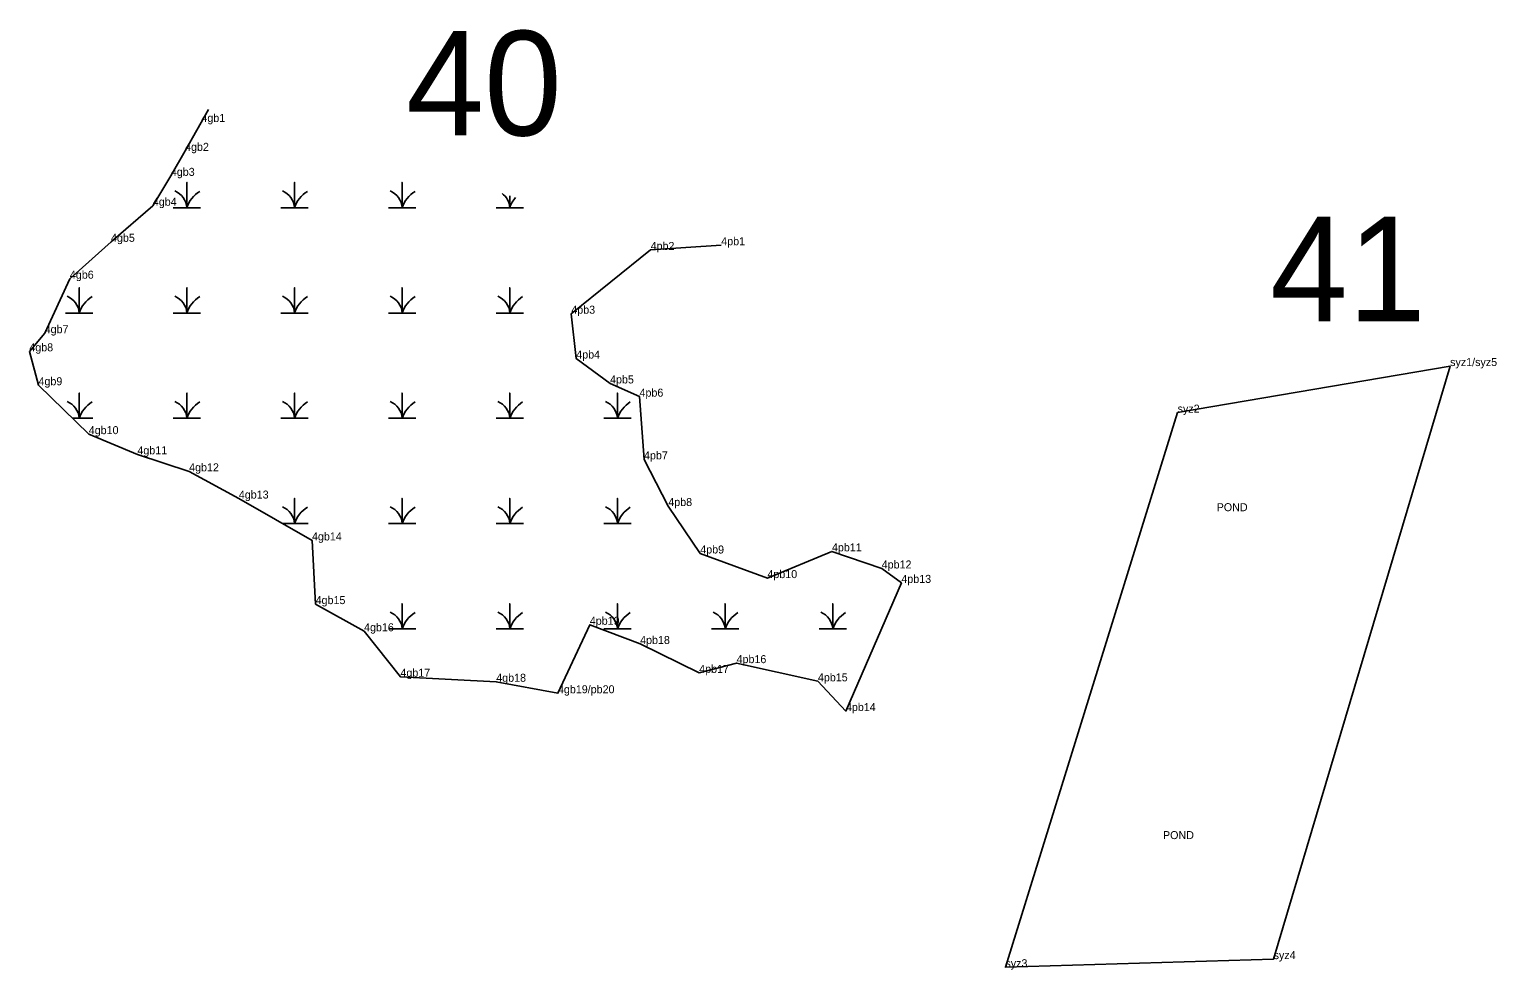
# Model space of a CAD drawing. Extents: x 2072529 to 2268796, y 436423 to 470397.
# Drawn here: x 2107562 to 2108478, y 456169 to 456756 of the extents above; entities that cross this region are included whole.
import ezdxf

# ---------------------------------------------------------------- set-up
doc = ezdxf.new("R2010")
doc.units = 0
for name, color, linetype in [('Default', 7, 'Continuous'), ('Exist Environmental Wetland Boundary', 7, 'Continuous'), ('Exist Environmental Wetland Boundary Cogo Comment', 7, 'Continuous'), ('Exist Environmental Wetland Boundary Cogo Point CELL', 7, 'Continuous'), ('Exist Hydro Jurisdictional Stream or Body of Water NEU Mitigable', 7, 'Continuous'), ('Exist Hydro Jurisdictional Stream or Body of Water NEU Mitigable Cogo Comment', 7, 'Continuous'), ('Exist Hydro Swamp or Marsh', 7, 'Continuous')]:
    doc.layers.add(name, color=color, linetype=linetype)

msp = doc.modelspace()

# ---------------------------------------------------------------- linework, layer by layer
at = {"layer": 'Exist Environmental Wetland Boundary'}
msp.add_lwpolyline([(2107673.67, 456706.2), (2107659.06, 456680.3), (2107650.18, 456664.67), (2107638.9, 456646.02), (2107612.8, 456623.48), (2107587.1, 456600.42), (2107571.35, 456566.38), (2107561.78, 456555.03), (2107567.49, 456533.84), (2107598.9, 456503.29), (2107629.27, 456490.66), (2107661.59, 456480.04), (2107692.65, 456463.02), (2107738.34, 456436.87), (2107740.6, 456397.08), (2107770.87, 456380.11), (2107793.58, 456351.7), (2107853.42, 456348.56), (2107891.98, 456341.37), (2107911.87, 456384.17), (2107943.3, 456372.16), (2107980.19, 456354.11), (2108003.54, 456360.19), (2108054.36, 456348.84), (2108071.85, 456330.26), (2108106.48, 456410.34), (2108094.21, 456419.35), (2108063.12, 456430.04), (2108022.81, 456413.35), (2107980.85, 456428.71), (2107960.9, 456458.37), (2107945.74, 456487.53), (2107942.92, 456526.73), (2107924.53, 456534.97), (2107903.4, 456550.54), (2107900.32, 456578.54), (2107949.86, 456618.38), (2107993.96, 456621.34)], dxfattribs=at)
at = {"layer": 'Exist Environmental Wetland Boundary Cogo Point CELL'}
for p, q in [((2107669.26, 456698.37), (2107669.26, 456698.37)), ((2107659.06, 456680.3), (2107659.06, 456680.3)), ((2107650.18, 456664.67), (2107650.18, 456664.67)), ((2107638.9, 456646.02), (2107638.9, 456646.02)), ((2107612.8, 456623.48), (2107612.8, 456623.48)), ((2107949.86, 456618.38), (2107949.86, 456618.38)), ((2107993.96, 456621.34), (2107993.96, 456621.34)), ((2107587.1, 456600.42), (2107587.1, 456600.42)), ((2107900.32, 456578.54), (2107900.32, 456578.54)), ((2107571.35, 456566.38), (2107571.35, 456566.38)), ((2107561.78, 456555.03), (2107561.78, 456555.03)), ((2107903.4, 456550.54), (2107903.4, 456550.54)), ((2108449.26, 456545.83), (2108449.26, 456545.83)), ((2108449.26, 456545.83), (2108449.26, 456545.83)), ((2107567.49, 456533.84), (2107567.49, 456533.84)), ((2107924.53, 456534.97), (2107924.53, 456534.97)), ((2107942.92, 456526.73), (2107942.92, 456526.73)), ((2108279.04, 456516.71), (2108279.04, 456516.71)), ((2108279.04, 456516.71), (2108279.04, 456516.71)), ((2107598.9, 456503.29), (2107598.9, 456503.29)), ((2107629.27, 456490.66), (2107629.27, 456490.66)), ((2107661.59, 456480.04), (2107661.59, 456480.04)), ((2107945.74, 456487.53), (2107945.74, 456487.53)), ((2107692.65, 456463.02), (2107692.65, 456463.02)), ((2107960.9, 456458.37), (2107960.9, 456458.37)), ((2107738.34, 456436.87), (2107738.34, 456436.87)), ((2107980.85, 456428.71), (2107980.85, 456428.71)), ((2108063.12, 456430.04), (2108063.12, 456430.04)), ((2108094.21, 456419.35), (2108094.21, 456419.35)), ((2108022.81, 456413.35), (2108022.81, 456413.35)), ((2108106.48, 456410.34), (2108106.48, 456410.34)), ((2107740.6, 456397.08), (2107740.6, 456397.08)), ((2107770.87, 456380.11), (2107770.87, 456380.11)), ((2107911.87, 456384.17), (2107911.87, 456384.17)), ((2107943.3, 456372.16), (2107943.3, 456372.16)), ((2108003.54, 456360.19), (2108003.54, 456360.19)), ((2107793.58, 456351.7), (2107793.58, 456351.7)), ((2107980.19, 456354.11), (2107980.19, 456354.11)), ((2107853.42, 456348.56), (2107853.42, 456348.56)), ((2107891.98, 456341.37), (2107891.98, 456341.37)), ((2108054.36, 456348.84), (2108054.36, 456348.84)), ((2108071.85, 456330.26), (2108071.85, 456330.26)), ((2108171.47, 456170.18), (2108171.47, 456170.18)), ((2108171.47, 456170.18), (2108171.47, 456170.18)), ((2108339.01, 456175.25), (2108339.01, 456175.25)), ((2108339.01, 456175.25), (2108339.01, 456175.25))]:
    msp.add_line(p, q, dxfattribs=at)
at = {"layer": 'Exist Hydro Jurisdictional Stream or Body of Water NEU Mitigable'}
msp.add_lwpolyline([(2108279.04, 456516.71), (2108449.26, 456545.83), (2108339.01, 456175.25), (2108171.47, 456170.18)], close=True, dxfattribs=at)
at = {"layer": 'Exist Hydro Swamp or Marsh'}
for points in [[(2107651.55, 456644.78), (2107660.16, 456644.78), (2107660.16, 456660.56), (2107660.16, 456644.78), (2107668.76, 456644.78)], [(2107718.8, 456644.78), (2107727.41, 456644.78), (2107727.41, 456660.56), (2107727.41, 456644.78), (2107736.01, 456644.78)], [(2107786.05, 456644.78), (2107794.66, 456644.78), (2107794.66, 456660.56), (2107794.66, 456644.78), (2107803.26, 456644.78)], [(2107853.3, 456644.78), (2107861.91, 456644.78), (2107861.91, 456652.27)], [(2107861.91, 456652.27), (2107861.91, 456644.78), (2107870.51, 456644.78)], [(2107584.3, 456578.98), (2107592.91, 456578.98), (2107592.91, 456594.76), (2107592.91, 456578.98), (2107601.51, 456578.98)], [(2107651.55, 456578.98), (2107660.16, 456578.98), (2107660.16, 456594.76), (2107660.16, 456578.98), (2107668.76, 456578.98)], [(2107718.8, 456578.98), (2107727.41, 456578.98), (2107727.41, 456594.76), (2107727.41, 456578.98), (2107736.01, 456578.98)], [(2107786.05, 456578.98), (2107794.66, 456578.98), (2107794.66, 456594.76), (2107794.66, 456578.98), (2107803.26, 456578.98)], [(2107853.3, 456578.98), (2107861.91, 456578.98), (2107861.91, 456594.76), (2107861.91, 456578.98), (2107870.51, 456578.98)], [(2107588.74, 456513.18), (2107592.91, 456513.18), (2107592.91, 456528.96), (2107592.91, 456513.18), (2107601.51, 456513.18)], [(2107651.55, 456513.18), (2107660.16, 456513.18), (2107660.16, 456528.96), (2107660.16, 456513.18), (2107668.76, 456513.18)], [(2107718.8, 456513.18), (2107727.41, 456513.18), (2107727.41, 456528.96), (2107727.41, 456513.18), (2107736.01, 456513.18)], [(2107786.05, 456513.18), (2107794.66, 456513.18), (2107794.66, 456528.96), (2107794.66, 456513.18), (2107803.26, 456513.18)], [(2107853.3, 456513.18), (2107861.91, 456513.18), (2107861.91, 456528.96), (2107861.91, 456513.18), (2107870.51, 456513.18)], [(2107920.55, 456513.18), (2107929.16, 456513.18), (2107929.16, 456528.96), (2107929.16, 456513.18), (2107937.76, 456513.18)], [(2107719.98, 456447.38), (2107727.41, 456447.38), (2107727.41, 456463.16), (2107727.41, 456447.38), (2107736.01, 456447.38)], [(2107786.05, 456447.38), (2107794.66, 456447.38), (2107794.66, 456463.16), (2107794.66, 456447.38), (2107803.26, 456447.38)], [(2107853.3, 456447.38), (2107861.91, 456447.38), (2107861.91, 456463.16), (2107861.91, 456447.38), (2107870.51, 456447.38)], [(2107920.55, 456447.38), (2107929.16, 456447.38), (2107929.16, 456463.16), (2107929.16, 456447.38), (2107937.76, 456447.38)], [(2107786.05, 456381.58), (2107794.66, 456381.58), (2107794.66, 456397.36), (2107794.66, 456381.58), (2107803.26, 456381.58)], [(2107853.3, 456381.58), (2107861.91, 456381.58), (2107861.91, 456397.36), (2107861.91, 456381.58), (2107870.51, 456381.58)], [(2107920.55, 456381.58), (2107929.16, 456381.58), (2107929.16, 456397.36), (2107929.16, 456381.58), (2107937.76, 456381.58)], [(2107987.8, 456381.58), (2107996.41, 456381.58), (2107996.41, 456397.36), (2107996.41, 456381.58), (2108005.01, 456381.58)], [(2108055.05, 456381.58), (2108063.66, 456381.58), (2108063.66, 456397.36), (2108063.66, 456381.58), (2108072.26, 456381.58)]]:
    msp.add_lwpolyline(points, dxfattribs=at)
for centre, radius, start, end in [((2107647.89, 456643.89), 12.3, 4.14034, 67.53497), ((2107678.4, 456638.72), 19.22, 122.12745, 161.62219), ((2107715.14, 456643.89), 12.3, 4.14034, 67.53497), ((2107745.65, 456638.72), 19.22, 122.12745, 161.62219), ((2107782.39, 456643.89), 12.3, 4.14034, 67.53497), ((2107812.9, 456638.72), 19.22, 122.12745, 161.62219), ((2107849.64, 456643.89), 12.3, 4.14034, 53.11148), ((2107880.15, 456638.72), 19.22, 139.53615, 161.62219), ((2107580.64, 456578.09), 12.3, 4.14034, 67.53497), ((2107611.15, 456572.92), 19.22, 122.12745, 161.62219), ((2107647.89, 456578.09), 12.3, 4.14034, 67.53497), ((2107678.4, 456572.92), 19.22, 122.12745, 161.62219), ((2107715.14, 456578.09), 12.3, 4.14034, 67.53497), ((2107745.65, 456572.92), 19.22, 122.12745, 161.62219), ((2107782.39, 456578.09), 12.3, 4.14034, 67.53497), ((2107812.9, 456572.92), 19.22, 122.12745, 161.62219), ((2107849.64, 456578.09), 12.3, 4.14034, 67.53497), ((2107880.15, 456572.92), 19.22, 122.12745, 161.62219), ((2107580.64, 456512.29), 12.3, 4.14034, 67.53497), ((2107611.15, 456507.12), 19.22, 122.12745, 161.62219), ((2107647.89, 456512.29), 12.3, 4.14034, 67.53497), ((2107678.4, 456507.12), 19.22, 122.12745, 161.62219), ((2107715.14, 456512.29), 12.3, 4.14034, 67.53497), ((2107745.65, 456507.12), 19.22, 122.12745, 161.62219), ((2107782.39, 456512.29), 12.3, 4.14034, 67.53497), ((2107812.9, 456507.12), 19.22, 122.12745, 161.62219), ((2107849.64, 456512.29), 12.3, 4.14034, 67.53497), ((2107880.15, 456507.12), 19.22, 122.12745, 161.62219), ((2107916.89, 456512.29), 12.3, 4.14034, 67.53497), ((2107947.4, 456507.12), 19.22, 122.12745, 161.62219), ((2107715.14, 456446.49), 12.3, 4.14034, 67.53497), ((2107745.65, 456441.32), 19.22, 122.12745, 161.62219), ((2107782.39, 456446.49), 12.3, 4.14034, 67.53497), ((2107812.9, 456441.32), 19.22, 122.12745, 161.62219), ((2107849.64, 456446.49), 12.3, 4.14034, 67.53497), ((2107880.15, 456441.32), 19.22, 122.12745, 161.62219), ((2107916.89, 456446.49), 12.3, 4.14034, 67.53497), ((2107947.4, 456441.32), 19.22, 122.12745, 161.62219), ((2107782.39, 456380.69), 12.3, 4.14034, 67.53497), ((2107812.9, 456375.52), 19.22, 122.12745, 161.62219), ((2107849.64, 456380.69), 12.3, 4.14034, 67.53497), ((2107880.15, 456375.52), 19.22, 122.12745, 161.62219), ((2107916.89, 456380.69), 12.3, 4.14034, 67.53497), ((2107947.4, 456375.52), 19.22, 122.12745, 161.62219), ((2107984.14, 456380.69), 12.3, 4.14034, 67.53497), ((2108014.65, 456375.52), 19.22, 122.12745, 161.62219), ((2108051.39, 456380.69), 12.3, 4.14034, 67.53497), ((2108081.9, 456375.52), 19.22, 122.12745, 161.62219)]:
    msp.add_arc(centre, radius, start, end, dxfattribs=at)

# ---------------------------------------------------------------- texts
at = {"layer": 'Default'}
for s, p in [('40', (2107797.23, 456689.92)), ('41', (2108336.8, 456573.74))]:
    msp.add_text(s, height=65.34, dxfattribs=at).set_placement(p)
at = {"layer": 'Exist Environmental Wetland Boundary Cogo Comment'}
for s, p in [('4gb1', (2107669.26, 456698.37)), ('4gb2', (2107659.06, 456680.3)), ('4gb3', (2107650.18, 456664.67)), ('4gb4', (2107638.9, 456646.02)), ('4gb5', (2107612.8, 456623.48)), ('4pb1', (2107993.96, 456621.34)), ('4pb2', (2107949.86, 456618.38)), ('4gb6', (2107587.1, 456600.42)), ('4pb3', (2107900.32, 456578.54)), ('4gb7', (2107571.35, 456566.38)), ('4gb8', (2107561.78, 456555.03)), ('4pb4', (2107903.4, 456550.54)), ('4gb9', (2107567.49, 456533.84)), ('4pb5', (2107924.53, 456534.97)), ('4pb6', (2107942.92, 456526.73)), ('4gb10', (2107598.9, 456503.29)), ('4gb11', (2107629.27, 456490.66)), ('4pb7', (2107945.74, 456487.53)), ('4gb12', (2107661.59, 456480.04)), ('4gb13', (2107692.65, 456463.02)), ('4pb8', (2107960.9, 456458.37)), ('4gb14', (2107738.34, 456436.87)), ('4pb9', (2107980.85, 456428.71)), ('4pb11', (2108063.12, 456430.04)), ('4pb12', (2108094.21, 456419.35)), ('4pb10', (2108022.81, 456413.35)), ('4pb13', (2108106.48, 456410.34)), ('4gb15', (2107740.6, 456397.08)), ('4pb19', (2107911.87, 456384.17)), ('4gb16', (2107770.87, 456380.11)), ('4pb18', (2107943.3, 456372.16)), ('4pb16', (2108003.54, 456360.19)), ('4gb17', (2107793.58, 456351.7)), ('4gb18', (2107853.42, 456348.56)), ('4pb17', (2107980.19, 456354.11)), ('4pb15', (2108054.36, 456348.84)), ('4gb19/pb20', (2107891.98, 456341.37)), ('4pb14', (2108071.85, 456330.26))]:
    msp.add_text(s, height=5, dxfattribs=at).set_placement(p)
at = {"layer": 'Exist Hydro Jurisdictional Stream or Body of Water NEU Mitigable Cogo Comment'}
for s, p in [('syz1/syz5', (2108449.26, 456545.83)), ('syz2', (2108279.04, 456516.71)), ('POND', (2108303.45, 456455.13)), ('POND', (2108269.9, 456250.25)), ('syz4', (2108339.01, 456175.25)), ('syz3', (2108171.47, 456170.18))]:
    msp.add_text(s, height=5, dxfattribs=at).set_placement(p)

doc.saveas('drawing.dxf')
